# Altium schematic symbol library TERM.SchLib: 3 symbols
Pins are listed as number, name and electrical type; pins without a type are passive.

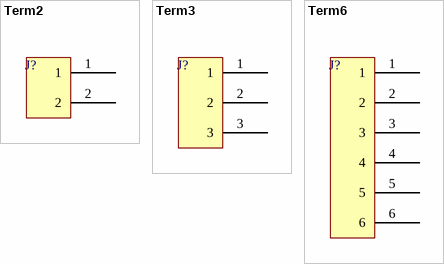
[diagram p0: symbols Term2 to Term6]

## Term2
designator J?
pins: 1, 2

## Term3
designator J?
footprint TERM3-0.14_Bottom
footprint TERM0.2_Bottom
pins: 1, 2, 3

## Term6
designator J?
footprint TERM6-0.14_Bottom
pins: 1, 2, 3, 4, 5, 6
